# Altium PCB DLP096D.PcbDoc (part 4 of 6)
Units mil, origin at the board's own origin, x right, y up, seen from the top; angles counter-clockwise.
Board outline 4950 x 3159.45 mil, 8 copper layers (Top Layer, GND1, SIGNAL1, POWER1, POWER2, SIGNAL2, GND2, Bottom Layer), stack 60.4 mil thick; 328 components, 223 nets, 1380 pads, 856 vias.
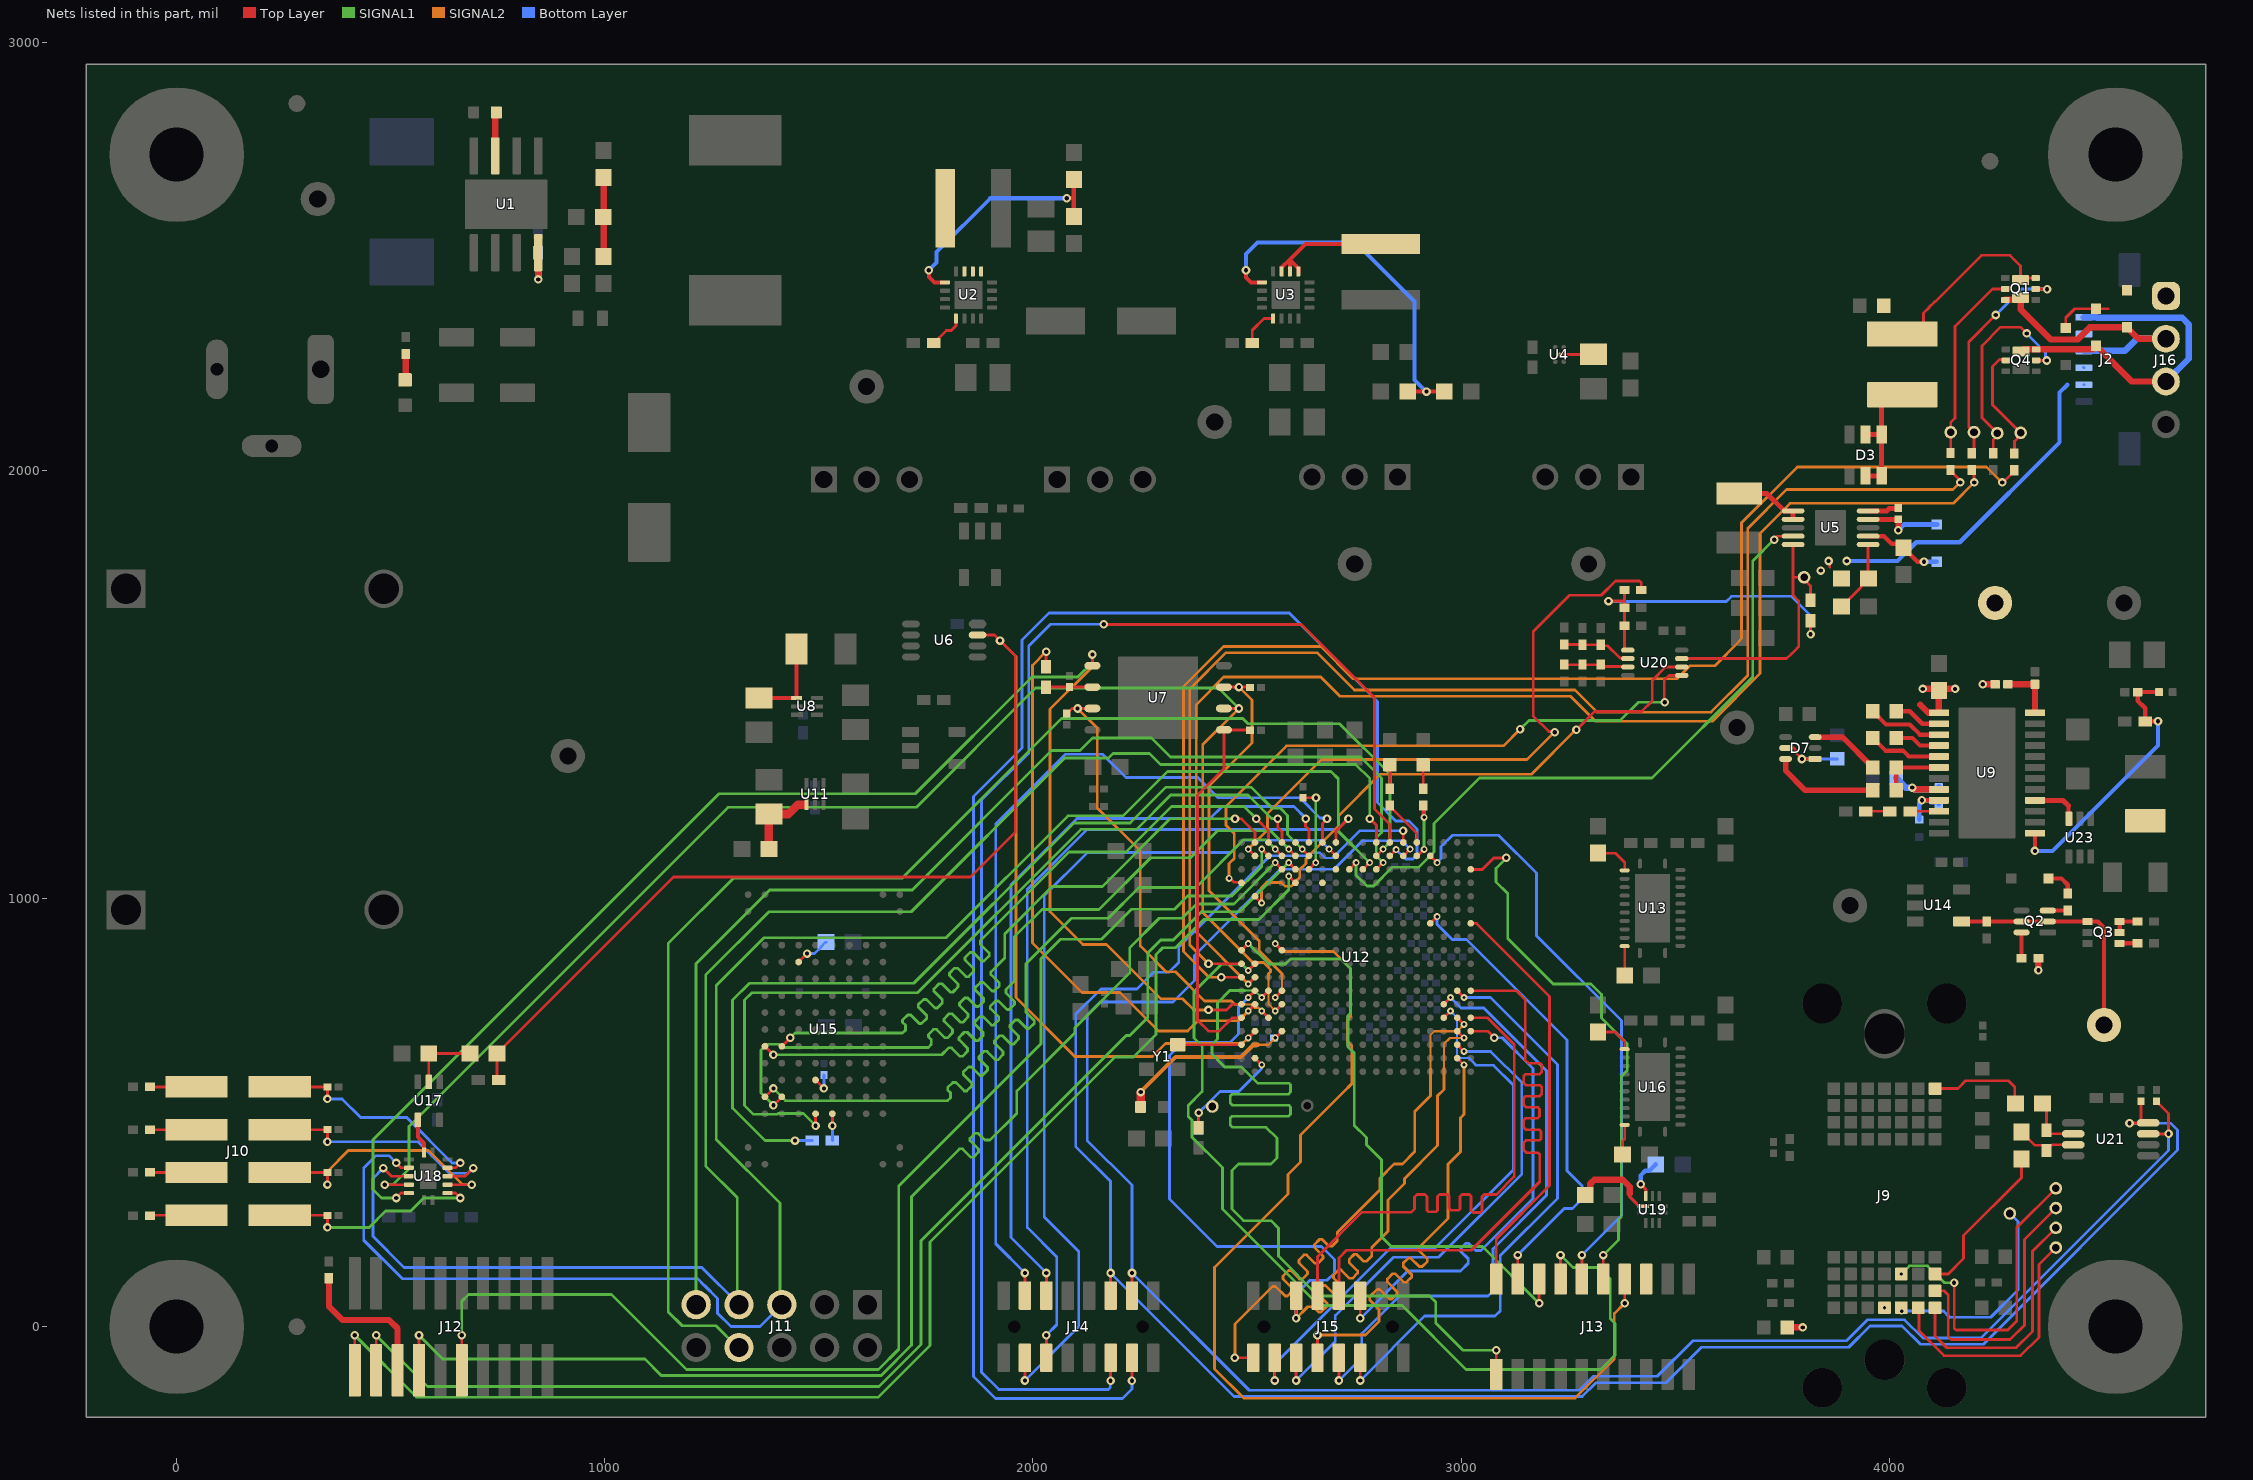
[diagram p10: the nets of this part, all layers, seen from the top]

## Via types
v1: diameter 20, hole 10, Top Layer to Bottom Layer, tented top, 596 vias
v2: diameter 16, hole 8, Top Layer to Bottom Layer, tented both sides, 126 vias
v3: diameter 16, hole 8.01, Top Layer to Bottom Layer, tented top, 63 vias
v4: diameter 19.68, hole 7.87, Top Layer to Bottom Layer, 37 vias
v5: diameter 16, hole 8.02, Top Layer to Bottom Layer, tented bottom, 22 vias
v6: diameter 24.8, hole 12.99, Top Layer to Bottom Layer, 6 vias
v7: diameter 19.68, hole 7.87, Top Layer to Bottom Layer, tented both sides, 6 vias

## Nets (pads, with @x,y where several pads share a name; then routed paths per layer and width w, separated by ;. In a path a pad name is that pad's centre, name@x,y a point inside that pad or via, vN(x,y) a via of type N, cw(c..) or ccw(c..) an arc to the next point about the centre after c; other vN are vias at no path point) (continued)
GPMC_AD7: J13.19 U12.M3 | length 2236.3
  Top Layer w6.5: v2(2534.33,768.95) U12.M3@2550.08,784.7 ; J13.19@3082.19,-111.32 v1(3082.19,-55.1)
  SIGNAL1 w5: 2495.5,784.95 2518.33,784.95 v2(2534.33,768.95)
  SIGNAL1 w6.5: 2495.5,784.95 2459.64,784.95 2431.08,756.38 2431.08,671.69 2418.03,658.65 2418.03,636.62 2440.47,614.19 2447.86,606.79 2486.79,606.79 2524.79,568.79 2597.91,568.79 2601.72,564.98 2601.72,548.01 2596.73,543.02 2464.64,543.02 2460.84,539.21 2460.84,522.24 2465.83,517.25 2597.91,517.25 2601.72,513.44 2601.72,496.47 2596.73,491.48 2464.64,491.48 2460.84,487.67 2460.84,470.7 2465.83,465.71 2544.53,465.71 2569.77,440.47 2569.77,393.93 2555.62,379.78 2479.74,379.78 2464.66,364.7 2464.66,274.82 2491.77,247.72 2555.51,247.72 2573.19,230.04 2573.19,164.79 2666.06,71.92 2926.5,71.92 2940.69,57.72 2940.69,8.97 3004.76,-55.1 v1(3082.19,-55.1)
GPMC_ADVn_ALE: J13.12 U12.B15 | length 1402.7
  Top Layer w6.5: U12.B15@2928.03,1099.66 v2(2943.78,1083.91) ; J13.12@3282.19,111.13 v1(3282.19,167.35)
  Bottom Layer w6.5: v2(2943.78,1083.91) 2953.36,1093.49 2953.36,1121.52 2979.73,1147.89 3087.65,1147.89 3175.95,1059.58 3175.95,913.14 3374.31,714.78 3374.31,259.47 v1(3282.19,167.35)
GPMC_BE0n_CLE: J13.10 U12.C18 | length 1290.3
  Top Layer w6.5: U12.C18@3022.52,1068.17 3049.34,1068.17 3076.19,1095.01 v1(3105.67,1095.01) ; J13.10@3332.19,111.13 v1(3332.19,167.35)
  SIGNAL1 w6.5: v1(3105.67,1095.01) 3081.3,1070.64 3081.3,1038.93 3108.82,1011.41 3108.82,906.78 3215.24,800.36 3303.63,800.36 3327.73,776.26 3327.73,720.98 3388.17,660.54 3388.17,598.08 3373.84,583.74 3373.84,255.83 3367.57,249.56 3367.57,202.73 v1(3332.19,167.35)
GPMC_CSn0: J13.8 U12.J4 | length 2494.1
  Top Layer w6.5: v2(2565.82,894.94) U12.J4@2581.57,879.19 ; v1(3382.19,54.91) J13.8@3382.19,111.13
  SIGNAL2 w6.5: v2(2565.82,894.94) 2584.25,876.52 2701.72,876.52 2741.53,836.71 2741.53,723.94 2734.02,716.44 2734.02,666.02 2744.49,655.55 2744.49,567.57 2723.83,546.91 2624.76,447.84 2624.76,384.55 2595.67,355.45 2595.67,310.4 2423.99,138.72 2423.99,-98.59 2492.34,-166.94 3265.93,-166.94 3357.83,-75.04 3357.83,30.54 v1(3382.19,54.91)
GPMC_LOCK: J13.6
GPMC_OEn_REn: J13.16 U12.J1 | length 1445.2
  Top Layer w6.5: U12.J1@2487.08,879.19 v2(2502.83,894.94) ; v1(3182.19,54.91) J13.16@3182.19,111.13
  SIGNAL1 w6.5: v2(2502.83,894.94) 2550.88,846.89 2589.29,846.89 2601.41,859.02 2719.21,859.02 2741.64,836.59 2741.64,732.82 2735.95,727.12 2735.95,653.31 2750.42,638.83 2750.42,470.25 2779.1,441.57 2779.1,424.99 2814.04,390.05 2814.04,209.97 2836.89,187.12 3049.98,187.12 v1(3182.19,54.91)
GPMC_WAIT0: J13.20 U12.G18 | length 966.4
  Top Layer w6.5: U12.G18@3022.52,942.18 3035.72,942.18 3206.39,771.51 3206.39,329.58 3082.19,205.38 J13.20@3082.19,111.13
GPMC_WEn: J13.14 U12.K2 | length 2207.1
  Top Layer w6.5: v2(2502.83,831.95) U12.K2@2518.58,847.69 ; J13.14@3232.19,111.13 v1(3232.19,167.35)
  SIGNAL1 w6.5: v2(2502.83,831.95) 2488.23,846.55 2440.43,846.55 2376.1,782.22 2376.1,674.73 2395.15,655.68 2395.15,549.2 2362.78,516.83 2362.78,490.7 2371.39,482.09 2371.39,442.62 2442.38,371.63 2442.38,275.27 2668.28,49.37 2862.55,49.37 3011.69,-99.77 3326.16,-99.77 3359.49,-66.44 3359.49,7.75 3348.41,18.84 3348.41,111.19 3321.08,138.52 3261.02,138.52 v1(3232.19,167.35)
GPMC_WPn: J13.18 U12.G15 | length 1102.7
  Top Layer w6.5: U12.G15@2928.03,942.18 v2(2943.78,957.93) ; J13.18@3132.19,111.13 v1(3132.19,167.35)
  Bottom Layer w6.5: v2(2943.78,957.93) 2943.78,940.07 2979.28,904.57 3012.89,904.57 3247.59,669.87 3247.59,364.17 3282.88,328.88 3282.88,299.2 3259.76,276.08 3240.93,276.08 v1(3132.19,167.35)
GREEN_CATH: D9.2 J2.1 J16.3 Q4.6 Q4.7 | length 786
  Top Layer w15: Q4.7@4307.78,2277.85 4312.71,2282.77 Q4.6@4343.22,2282.77 4474.88,2282.77 D9.2@4483.21,2291.1 4566.69,2207.62 J16.3@4646.25,2207.62
  Bottom Layer w15: J2.1@4454.68,2357.79 4484.78,2357.79 4486.25,2356.32 4684.24,2356.32 4699.79,2340.76 4699.79,2261.16 J16.3@4646.25,2207.62
GREEN_LED_EN: R80.1 U12.L1 | length 3182.1
  Top Layer w6.5: v1(2439.95,816.2) U12.L1@2487.08,816.2 ; v1(4263.67,1971.88) 4265.76,1971.88 4292.24,1998.36 R80.1@4292.24,2000.33 R80.1@4292.55,2000.02
  SIGNAL2 w6.5: v1(2439.95,816.2) 2411.57,816.2 2351.69,876.09 2351.69,1495.14 2445.22,1588.67 2672.35,1588.67 2747.73,1513.3 3362.61,1513.3 3503.8,1513.3 3534.39,1543.88 3592.57,1543.88 3648.81,1600.12 3648.81,1601.31 3654.99,1607.49 3654.99,1877.78 3785.29,2008.08 4227.47,2008.08 v1(4263.67,1971.88)
I2C0_SCL: J14.6 R86.1 U12.A13 U21.8 | length 4851.7
  Top Layer w6.5: J14.6@2181.28,72.44 v1(2181.28,125.42) ; v1(2864.47,1158.59) 2864.75,1158.31 2864.75,1131.44 U12.A13@2865.04,1131.16 ; v1(4561.08,475.36) 4561.43,475.71 4604.5,475.71 U21.8@4604.84,476.05 4593.34,476.05 4588.16,481.23 R86.1@4588.16,526.69
  Bottom Layer w5: 2553.56,1099.91 2644.94,1099.91 2652,1106.97 2670.03,1106.97 2681.91,1095.09 2700.59,1095.09 2712.64,1107.14
  Bottom Layer w6.5: 2553.56,1099.91 2340.54,886.89 2340.54,850.64 2317.96,828.05 2281.98,828.05 2242.57,788.65 2158.57,788.65 2099.77,729.85 2099.77,421.33 2181.28,339.81 v1(2181.28,125.42) 2469.54,-162.84 3282.79,-162.84 3314.68,-130.95 3478.33,-130.95 3561.19,-48.08 3905.28,-48.08 3955.07,1.7 4030,1.7 4072.6,-40.89 4220.29,-40.89 4673.58,412.4 4673.58,459.1 4657.32,475.36 v1(4561.08,475.36) ; 2712.64,1107.14 2764.09,1158.59 v1(2864.47,1158.59)
I2C0_SDA: J14.4 R85.1 U12.B13 U21.7 | length 4682.7
  Top Layer w6.5: J14.4@2231.28,72.44 v1(2231.28,125.42) ; U12.B13@2865.04,1099.66 v2(2880.79,1115.41) ; R85.1@4624.63,526.82 4624.63,526.03 4652.46,498.2 v1(4652.46,450.35) 4652.4,450.4 4604.9,450.4 U21.7@4604.84,450.46 U21.7@4625.23,450.46
  Bottom Layer w5: 2591.54,1068.41 2696.47,1068.41
  Bottom Layer w6.5: 2591.54,1068.41 2578.86,1068.41 2377.07,866.63 2377.07,808.78 2326.93,758.64 2157.12,758.64 2126.56,728.09 2126.56,435.31 2231.28,330.59 v1(2231.28,125.42) 2505.17,-148.47 3276.83,-148.47 3309.5,-115.8 3458.19,-115.8 3541.2,-32.79 3899.83,-32.79 3948.7,16.08 4035.95,16.08 4078.55,-26.52 4214.33,-26.52 4652.46,411.61 v1(4652.46,450.35) ; 2696.47,1068.41 2703.19,1068.41 2769.71,1134.94 2861.26,1134.94 v2(2880.79,1115.41)
I2C1_SCL: U12.D7
I2C1_SDA: U12.C8
LED_ANODE: C70.1 D1.1 D9.1 D10.1 J2.2 J2.4 J2.5 J16.1 L4.2 Q1.6 Q1.7 R12.2 | length 1399.2
  Top Layer w6.5: v1(3858.2,1788.47) 3860.88,1785.79 3860.88,1774.02 ; R12.2@3879.93,1739.31 R12.2@3888.25,1747.63 ; R12.2@3887.27,1747.63 R12.2@3888.25,1747.63 ; R12.2@3900.86,1760.23 R12.2@3888.25,1747.63 ; L4.2@4030.55,2318.66 4053.67,2318.66 4080.19,2345.19 4080.19,2367.33 4092.94,2380.08 4092.94,2381.06 4105.69,2393.81 4106.68,2393.81 4215.2,2502.34 4282.19,2502.34 4306.7,2477.83 Q1.7@4306.7,2444.58 4311.62,2449.5 Q1.6@4342.13,2449.5 ; D10.1@4412.25,2332.92 4412.25,2356.6 4433.36,2377.72 D9.1@4483.21,2377.72 4511.75,2377.72 ; D1.1@4554.96,2420.93 D1.1@4563.77,2412.11 ; J16.1@4641.76,2412.11 J16.1@4646.25,2407.62
  Bottom Layer w6.5: J2.4@4453.59,2240.76 J2.4@4454.68,2239.68 ; J2.5@4454.49,2200.12 J2.5@4454.68,2200.31
  Bottom Layer w10: v1(3900.86,1788.47) 4019.07,1788.47 4062.93,1832.33 4164.66,1832.33 4397.86,2065.53 4397.86,2181.99 4416.01,2200.14
  other v1: 3839.75,1766.01
LED_DRV_EN: U5.9 U12.C9 | length 1618.8
  Top Layer w6.5: U12.C9@2739.05,1068.17 v2(2754.8,1083.91) ; v1(3731.25,1838.23) 3739.45,1846.43 U5.9@3775.35,1846.43
  SIGNAL1 w6.5: v2(2754.8,1083.91) 2754.8,1054.5 2780,1029.3 2796.03,1029.3 2840.03,1073.3 2901.23,1073.3 2936.93,1109.01 2936.93,1167.9 2936.93,1175.01 3043.29,1281.37 3445.82,1281.37 3681.26,1516.81 3681.26,1788.24 v1(3731.25,1838.23)
LIN2_RXD: J14.13 U12.B8 | length 2020.6
  Top Layer w6.5: v1(1981.28,-125.61) J14.13@1981.28,-72.63 ; v2(2691.81,1115.41) U12.B8@2707.56,1099.66
  Bottom Layer w6.5: v1(1981.28,-125.61) 2106.92,0.03 2106.92,175.56 2026.33,256.15 2026.33,1006.8 2127.22,1107.69 2462.33,1107.69 2490.66,1136.02 2671.2,1136.02 v2(2691.81,1115.41)
LIN2_TXD: J14.11 U12.A8 | length 2018.5
  Top Layer w6.5: J14.11@2031.28,-72.63 v1(2031.28,-19.66) ; U12.A8@2707.56,1131.16 2707.56,1157.09 v1(2736.82,1186.35)
  Bottom Layer w6.5: v1(2031.28,-19.66) 2055.57,4.62 2055.57,162.72 1986.82,231.46 1986.82,1021.85 2126.46,1161.5 2440.47,1161.5 2711.97,1161.5 2727.68,1177.21 v1(2736.82,1186.35)
MCAN2_RX: J14.5 U12.A12 | length 3383.1
  Top Layer w6.5: v1@2165.8,1640.39 2626.49,1640.39 2797.92,1468.96 2797.92,1234.56 2797.67,1234.31 2797.67,1208.92 2833.54,1173.05 U12.A12@2833.54,1131.16 ; v1(2181.23,-126.35) 2181.23,-72.68 J14.5@2181.28,-72.63
  Bottom Layer w6.5: v1(2165.06,1640.77) 2040.84,1640.77 1990.16,1590.09 1990.16,1340.36 1879.93,1230.13 1879.93,-106.4 1920.26,-146.73 2176.17,-146.73 2180.61,-142.29 2180.61,-126.97 v1(2181.23,-126.35)
MCAN2_TX: J14.3 U12.B12 | length 3679.3
  Top Layer w6.5: v1(2231.22,-126.35) 2231.22,-72.7 J14.3@2231.28,-72.63 ; U12.B12@2833.54,1099.66 v2(2848.21,1114.39)
  Bottom Layer w6.5: v1(2231.22,-126.35) 2231.22,-145.15 2208.84,-167.52 1912.68,-167.52 1861.27,-116.11 1861.27,1238.54 1974.6,1351.86 1974.6,1604.14 2037.23,1666.78 2598.47,1666.78 2804.72,1460.53 2804.72,1224.08 2847.35,1181.45 2878.02,1181.45 2891.57,1167.9 2897.28,1162.19 2897.28,1102.43 2887.22,1092.37 2870.23,1092.37 v2(2848.21,1114.39)
NetC1_1: C1.1 U1.7 | length 102.4
  Top Layer w15: U1.7@744.28,2734.87 744.28,2833.61 C1.1@746.89,2836.22
NetC2_1: C2.1 C3.2 R1.2 | length 185
  Top Layer w15: C3.2@997.4,2499.3 997.4,2591.79 R1.2@997.4,2684.27
NetC6_1: C6.1 U2.9 | length 85.7
  Top Layer w6.5: C6.1@1767.84,2297.32 1797.6,2327.09 1809.08,2327.09 1820.01,2338.02 U2.9@1820.03,2354.73
NetC8_1: C8.1 U3.9 | length 90.1
  Top Layer w6.5: C8.1@2512.18,2297.27 2512.18,2327.27 2539.64,2354.73 U3.9@2560.86,2354.73
NetC17_1: C17.1 D501.1 U5.4 | length 191.3
  Top Layer w11.81: U5.4@3950.54,1885.8 4020.99,1885.8 v1(4020.99,1860.31)
  Bottom Layer w11.81: v1(4020.99,1860.31) 4034.07,1873.39 D501.1@4110.9,1873.39
NetC17_2: C17.2 D3.1 D3.2 D3.5 D3.6 L4.1 U5.5 | length 371.8
  Top Layer w11.81: D3.5@3944.95,1987.45 D3.6@3982.35,1987.45 D3.1@3982.35,2083.91 ; D3.2@3944.95,2083.91 D3.1@3982.35,2083.91 ; U5.5@3950.54,1905.48 3994.12,1905.48 3999.7,1911.06 4020.12,1911.06 C17.2@4020.99,1911.94 ; L4.1@4030.55,2176.93 4005.97,2176.93 3982.35,2153.31 D3.1@3982.35,2083.91
NetC18_1: C18.1 D501.2 U5.2 | length 185.1
  Top Layer w10: U5.2@3950.54,1846.43 3987.85,1846.43 4005.52,1828.75 4024.12,1828.75 4066.1,1786.78 v1(4081.16,1786.78)
  Bottom Layer w10: v1(4081.16,1786.78) D501.2@4110.9,1786.78
NetC20_1: C20.1 R13.2 R14.2 R76.2 U20.1 | length 755.8
  Top Layer w6: R76.2@3815.8,1649.35 3816.16,1649 v1(3816.16,1617.65)
  Top Layer w6.5: v1(3344.3,1694.88) 3381.37,1694.88 ; R14.2@3381.37,1720.69 3381.37,1694.88 ; U20.1@3389.43,1580.2 3383.83,1580.2 3381.37,1582.66 C20.1@3381.37,1637.65 R13.2@3381.37,1679.17 3381.37,1694.88
  Bottom Layer w6.5: v1(3344.3,1694.88) 3345.6,1693.58 3619.36,1693.58 3631.72,1705.95 3771.76,1705.95 3816.16,1661.54 v1(3816.16,1617.65)
NetC21_1: C21.1 R12.1 U5.1 | length 170.6
  Top Layer w6.5: C21.1@3888.25,1682.72 3889.24,1682.72 3934.81,1728.3 3934.81,1732.18 3950.26,1747.63 3950.54,1747.63 U5.1@3950.54,1826.74
NetC27_1: C27.1 U9.14 | length 111.3
  Top Layer w10: C27.1@4016.62,1437.45 4048.05,1437.45 4077.05,1408.45 U9.14@4115.92,1408.45
NetC27_2: C27.2 U9.15 | length 177
  Top Layer w10: C27.2@3961.5,1437.45 3992.41,1406.54 4047.76,1406.54 4071.44,1382.86 U9.15@4115.92,1382.86
NetC29_2: C29.2 R20.1 R21.2 U9.1 | length 642.5
  Top Layer w10: v1(4340.33,1111.19) U9.1@4340.33,1152.54 ; v1(4627.66,1413.83) C29.2@4597.85,1413.83 4597.85,1444.44 4580.17,1462.12 R20.1@4580.17,1482.23 R21.2@4630.17,1482.23
  Bottom Layer w10: v1(4340.33,1111.19) 4381.27,1111.19 4627.66,1357.58 v1(4627.66,1413.83)
NetC33_1: C33.1 U9.16 | length 106.7
  Top Layer w10: C33.1@4016.62,1375.08 4053.93,1375.08 4071.75,1357.27 U9.16@4115.92,1357.27
NetC33_2: C33.2 U9.17 | length 172.4
  Top Layer w10: C33.2@3961.5,1375.08 3991.11,1345.48 4032.05,1345.48 4045.85,1331.68 U9.17@4115.92,1331.68
NetC34_1: C34.1 D7.3 | length 164.1
  Top Layer w13: D7.3@3826.84,1377.2 3890.38,1377.2 C34.1@3961.5,1306.09
NetC34_2: C34.2 C37.1 U9.18 | length 152.5
  Top Layer w10: C37.1@4016.62,1252.85 C34.2@4016.62,1306.09 U9.18@4115.92,1306.09
NetC37_2: C37.2 D7.6 | length 249.9
  Top Layer w13: D7.6@3757.81,1326.02 3757.81,1298.89 3803.84,1252.85 C37.2@3961.5,1252.85
NetC40_2: C40.2 R33.1 | length 59.7
  Top Layer w6.5: C40.2@3941.57,1203.72 R33.1@4001.26,1203.72
NetC51_1: C51.1 R46.1 U17.2 | length 162.2
  Top Layer w6.5: U17.2@588.87,571.84 C51.1@588.87,638.09 R46.1@684.85,638.09
NetC66_1: C66.1 R30.2 R49.2 U20.2 | length 162.3
  Top Layer w6: R30.2@3240.8,1593.39 3283.08,1593.39 R49.2@3283.55,1592.91 ; R49.2@3283.55,1592.91 C66.1@3326.3,1592.94 3328.62,1590.62 3342.13,1590.62
  Top Layer w6.5: 3342.13,1590.62 3371.12,1561.63 3388.32,1561.63 U20.2@3389.43,1560.52
NetC68_1: C68.1 R50.2 R51.2 U20.3 | length 150.9
  Top Layer w6: R50.2@3240.8,1546.26 3283.36,1546.26 R51.2@3283.55,1546.44 C68.1@3326.3,1546.43
  Top Layer w6.5: C68.1@3326.3,1546.07 3330.42,1541.94 3377.04,1541.94 3378.15,1540.83 U20.3@3389.43,1540.83
NetC72_1: C72.1 R83.1 U21.2 | length 132.1
  Top Layer w6.5: R83.1@4357.66,521.14 4367.32,511.47 C72.1@4367.32,458.79 4375.66,450.46 U21.2@4429.64,450.46
NetC72_2: C72.2 R84.1 U21.3 | length 145.7
  Top Layer w6.5: R84.1@4308.7,455.01 4308.7,454.02 4324.15,438.57 4325.14,438.57 4339.66,424.05 4358.76,424.05 C72.2@4367.32,415.49 ; C72.2@4367.32,411.55 C72.2@4367.32,415.49 ; U21.3@4429.64,424.87 4380.64,424.87 4379.82,424.05 4375.88,424.05 C72.2@4367.32,415.49
NetC504_1: C504.1 D7.1 D7.5 | length 166.1
  Top Layer w6.5: D7.5@3757.81,1351.61 3777.12,1351.61 3783.7,1345.03 3783.7,1338.43 v1(3796.1,1326.02) D7.1@3826.84,1326.02
  Bottom Layer w6.5: v1(3796.1,1326.02) C504.1@3878.72,1326.02
NetC505_1: C505.1 R503.1 U9.20 | length 176.6
  Top Layer w15: v1(4053.64,1259.16) 4057.9,1254.9 U9.20@4115.92,1254.9
  Bottom Layer w15: C505.1@4016.62,1281.53 4038.99,1259.16 v1(4053.64,1259.16) 4057.9,1254.9 4110.56,1254.9 R503.1@4115.92,1260.27
NetC526_1: C526.1 U15.E4 | length 83.7
  Top Layer w6.5: U15.E4@1452.77,851.78 v1(1472.46,871.47)
  Bottom Layer w6.5: v1(1472.46,871.47) 1489.96,871.47 1504.52,886.02 1504.52,887.01 1515.72,898.21 C526.1@1516.71,898.21
NetD2_2: D2.2 R4.1 | length 51.8
  Top Layer w15: D2.2@534.88,2220.31 R4.1@534.88,2272.07
NetD5_2: D5.2 R31.1 | length 55.6
  Top Layer w6.5: R31.1@2833.82,1256.42 D5.2@2833.82,1312.07
NetD6_2: D6.2 R32.1 | length 55.6
  Top Layer w6.5: R32.1@2911.38,1256.42 D6.2@2911.38,1312.07
NetD8_2: D8.2 R38.2 | length 72.3
  Top Layer w10: D8.2@4371.61,1046.98 4402.37,1046.98 4416.95,1032.4 R38.2@4416.95,1011.44
NetJ9_E13: J9.E13 TP20.1 | length 758.3
  Top Layer w6.5: v1(4151.39,102.67) 4151.95,102.11 4151.95,-4 4155.75,-7.8 4276.77,-7.8 4297.8,13.23 4297.8,231.93 TP20.1@4389.08,323.21
  SIGNAL1 w6.5: v5(4028.26,123.11) 4047.38,142.23 4089.64,142.23 4129.2,102.67 v1(4151.39,102.67)
NetJ9_E15: J9.E15 TP13.1 | length 498.8
  Top Layer w6.5: J9.E15@4028.26,44.37 4028.91,43.71 v5(4028.91,36.42)
  Bottom Layer w6.5: v5(4028.91,36.42) 4127.12,36.42 4141.4,22.14 4237.04,22.14 4300.66,85.76 4300.66,245.62 TP13.1@4281.77,264.5
NetJ9_F15: J9.F15 TP18.1 | length 602.5
  Top Layer w6.5: J9.F15@4067.63,44.37 4069.73,42.26 4069.73,-9.33 4128.08,-67.67 4306.99,-67.67 4349.58,-25.08 4349.58,145.34 TP18.1@4389.08,184.84
NetJ9_G2: J9.G2 R83.2 | length 238.8
  Top Layer w6.5: J9.G2@4107,556.18 4160.3,556.18 4178.47,574.35 4278.21,574.35 4293.26,559.3 4293.26,522.54 R83.2@4294.66,521.14
NetJ9_G13: J9.G13 R84.2 | length 370.4
  Top Layer w6.5: J9.G13@4107,123.11 4137.68,123.11 4173.72,159.15 4173.72,212.95 4308.7,347.93 R84.2@4308.7,392.01
NetJ9_G14: J9.G14 TP19.1 | length 639.9
  Top Layer w6.5: J9.G14@4107,83.74 4128.47,83.74 4137.57,74.64 4137.57,-22.83 4144.89,-30.15 4282.35,-30.15 4315.83,3.33 4315.83,203.84 TP19.1@4395.34,283.35
NetJ9_G15: J9.G15 TP21.1 | length 585.1
  Top Layer w6.5: J9.G15@4107,44.37 4107,-21.66 4134.41,-49.07 4296.17,-49.07 4334.38,-10.85 4334.38,176.27 TP21.1@4389.08,230.96
NetJ10_2: J10.2 R71.2 | length 111.4
  Top Layer w6.5: R71.2@-65.59,260.2 J10.2@45.83,260.2
NetJ10_4: J10.4 R68.2 | length 111.4
  Top Layer w6.5: R68.2@-65.59,360.2 J10.4@45.83,360.2
NetJ10_6: J10.6 R64.2 | length 111.4
  Top Layer w6.5: R64.2@-65.59,460.2 J10.6@45.83,460.2
NetJ10_8: J10.8 R48.2 | length 111.4
  Top Layer w6.5: R48.2@-65.59,560.2 J10.8@45.83,560.2
NetJ12_5: J12.5 R75.2 | length 344.9
  Top Layer w14.5: R75.2@355.48,113.28 355.48,47.71 387.65,15.54 496.21,15.54 515.94,-4.19 J12.5@515.94,-101.59
NetL2_1: L2.1 U2.1 U2.2 U2.3
NetL3_1: L3.1 U3.1 U3.2 U3.3 | length 326.1
  Top Layer w9.4: U3.3@2580.55,2464.97 2580.55,2473.42 2600.23,2493.1 ; U3.2@2600.23,2464.97 2600.23,2491.74 ; U3.1@2619.92,2464.97 2619.92,2472.06 2600.23,2491.74 ; L3.1@2812.21,2528.89 2636.02,2528.89 2600.23,2493.1 ; 2600.23,2491.74 2600.23,2493.1
NetL5_1: L5.1 U4.B2 | length 79.9
  Top Layer w8: U4.B2@3229.8,2270.72 L5.1@3309.74,2270.72
NetL6_1: L6.1 U9.4 U23.6 | length 120.1
  Top Layer w10: 4418.43,1216.91 4418.43,1203.63 U23.6@4421.2,1200.86 ; L6.1@4578.1,1182.03 L6.1@4597.78,1182.03
  Top Layer w12: U9.4@4340.33,1229.31 4406.03,1229.31 4418.43,1216.91
NetQ1_2: Q1.2 R78.2 TP2.1 | length 453.9
  Top Layer w6.5: R78.2@4143.06,2040.67 4143.43,2041.04 4143.43,2111.65 4153.85,2122.08 4153.85,2336.56 4241.21,2423.91 Q1.2@4271.26,2423.91
NetQ1_5: Q1.5 R79.2 TP3.1 | length 527.5
  Top Layer w6: R79.2@4192.79,2040.11 4197.91,2045.23 TP3.1@4197.91,2089.2
  Top Layer w6.5: TP3.1@4197.91,2089.2 4185.72,2101.39 4185.72,2300.19 v1@4248.39,2362.86 ; Q1.5@4342.13,2423.91 4342.37,2423.68 4368.4,2423.68 v1(4368.64,2423.44)
  Bottom Layer w6.5: v1(4248.75,2363) 4309.19,2423.44 v1(4368.64,2423.44)
NetQ2_2: Q2.2 Q2.5 Q3.4 R39.2 TP12.1 U14.4 | length 566
  Top Layer w10: U14.4@4168.92,946.48 R39.2@4227.71,946.48 Q2.5@4309.04,946.48 Q2.2@4370.2,946.48 Q3.4@4463.25,946.48 4486.97,946.48 4501.69,931.76 TP12.1@4501.69,704.62
NetQ2_3: Q2.3 R38.1 | length 46.8
  Top Layer w10: Q2.3@4370.2,972.07 R38.1@4416.95,972.07
NetQ2_6: Q2.6 R42.1 | length 60.6
  Top Layer w10: R42.1@4309.04,860.32 Q2.6@4309.04,920.89
NetQ3_1: Q3.1 R41.2 | length 41.3
  Top Layer w10: Q3.1@4538.06,895.3 R41.2@4579.41,895.3
NetQ3_2: Q3.2 Q3.3 R40.2 | length 66.9
  Top Layer w10: Q3.2@4538.06,920.89 Q3.3@4538.06,946.48 R40.2@4579.41,946.48
NetQ4_2: Q4.2 R80.2 TP14.1 | length 274.7
  Top Layer w6.5: Q4.2@4272.35,2257.18 4270.51,2259.02 4257.61,2259.02 4241.43,2242.84 4241.43,2153.39 TP14.1@4306.86,2087.97 4306.86,2082.54 4292.24,2067.92 R80.2@4292.24,2039.7
NetQ4_5: Q4.5 R81.2 TP15.1 | length 504.8
  Top Layer w6: R81.2@4242.51,2040.11 4242.51,2070.91 4252.38,2080.78 TP15.1@4252.38,2087.15
  Top Layer w6.5: TP15.1@4252.38,2087.15 4216.44,2123.08 4216.44,2290.97 4260.07,2334.6 4306.15,2334.6 v1@4320.28,2320.46 ; Q4.5@4343.22,2257.18 4343.4,2256.99 4367.51,2256.99 v1(4367.7,2256.8)
  Bottom Layer w6.5: v1(4320.88,2319.96) 4365.04,2275.8 4365.04,2259.47 v1(4367.7,2256.8)
NetR6_2: R6.2 R9.1 U2.5 | length 567.9
  Top Layer w9.4: v1(1756.8,2467.85) 1756.8,2452.32 1769.74,2439.38 U2.5@1794.44,2439.38
  Top Layer w10: v1(2078.95,2635.71) 2079.66,2636.42 2095.46,2636.42 ; R9.1@2095.46,2593.12 2095.46,2636.42 ; R6.2@2095.46,2679.72 2095.46,2636.42
  Bottom Layer w9.4: v1(1756.8,2467.85) 1774.27,2485.32 1774.27,2509.74 1900.24,2635.71 v1(2078.95,2635.71)
NetR7_1: R7.1 R8.2 U3.5 | length 866.4
  Top Layer w9.4: v1(2497.63,2467.85) 2497.63,2451.11 2509.36,2439.38 U3.5@2535.27,2439.38
  Top Layer w10: R7.1@2875.37,2184.26 v1(2919.17,2184.26) R8.2@2960.59,2184.26
  Bottom Layer w9.4: v1(2497.63,2467.85) 2497.63,2505.78 2524.28,2532.43 2752.96,2532.43 2890.87,2394.51 2890.87,2211.46 2918.07,2184.26 v1(2919.17,2184.26)
NetR11_1: R11.1 U5.6 U5.7 | length 162.1
  Top Layer w11.81: R11.1@3649.76,1946.03 3714.13,1946.03 3754.68,1905.48 U5.6@3775.35,1905.48 U5.7@3775.35,1885.8
NetR15_2: R15.2 R24.1 U8.1 | length 201.6
  Top Layer w9.8: R24.1@1360.62,1468.49 U8.1@1447.66,1468.49 R15.2@1447.66,1583.01
NetR16_2: R16.2 R18.2 U7.6 | length 107.9
  Top Layer w6.5: R16.2@2031,1493.98 R18.2@2085.41,1493.98 U7.6@2138.92,1493.98
NetR17_2: R17.2 R19.1 U9.12 | length 129.7
  Top Layer w15: R19.1@4277.09,1500.46 R17.2@4340.33,1500.46 U9.12@4340.33,1434.04
NetR27_2: R27.2 R36.1 U11.1 | length 173.9
  Top Layer w20: R36.1@1383.27,1115.55 R27.2@1383.27,1197.49 1428.89,1197.49 1450.99,1219.58 1466.07,1219.58
NetR33_2: R33.2 U9.22 | length 67.4
  Top Layer w6.5: R33.2@4048.5,1203.72 U9.22@4115.92,1203.72
NetR34_2: R34.2 U13.2 | length 89.7
  Top Layer w6.5: R34.2@3319.63,1106.01 3360.06,1106.01 3382.11,1083.97 U13.2@3382.11,1065.87
NetR43_2: R43.2 U13.11 | length 68.7
  Top Layer w6.5: R43.2@3382.11,820.04 U13.11@3382.11,888.71
NetR44_2: R44.2 U16.2 | length 89.7
  Top Layer w6.5: R44.2@3319.63,688.52 3360.06,688.52 3382.11,666.48 U16.2@3382.11,648.38
NetR62_2: R62.2 R519.1 TP22.1 U12.U2 | length 290.3
  Top Layer w6.5: R62.2@2386.96,464.91 v1(2386.96,499.66) ; U12.U2@2518.58,627.22 v2(2534.33,611.47)
  Bottom Layer w6.5: R519.1@2386.96,464.91 v1(2386.96,499.66) 2411.27,523.97 2436.69,549.39 2480.54,549.39 2533.18,602.02 2533.18,610.33 v2(2534.33,611.47)
NetR66_2: R66.2 U16.11 | length 70.4
  Top Layer w6.5: R66.2@3377.11,402.55 3377.11,434.05 3382.11,439.05 U16.11@3382.11,470.85
NetR69_1: R69.1 U19.1 | length 198.6
  Top Layer w8: 3393.9,310.25 3393.9,303.25 3415.74,281.42 U19.1@3425.45,281.42
  Top Layer w15: R69.1@3289.83,307.91 3290.81,307.91 3302.01,319.11 3302.01,334.34 3310.8,343.13 3377.73,343.13 3393.9,326.95 3393.9,310.25
NetR76_1: R76.1 TP16.1 U5.10 U20.7 | length 614.3
  Top Layer w6.5: U20.7@3515.42,1560.52 3760.26,1560.52 3771.4,1571.66 3771.76,1571.66 3784.13,1584.04 3784.13,1584.39 3788.37,1588.63 3788.37,1695.35 3775.35,1708.37 3775.35,1751.12 ; U5.10@3775.35,1826.74 3775.35,1751.12 ; R76.1@3815.8,1696.6 3815.8,1730.43 3801.12,1745.11 TP16.1@3801.12,1750.42 3776.04,1750.42 3775.35,1751.12
NetR500_2: R500.2 U1.4 | length 124.6
  Top Layer w15: v1(844.28,2446.17) U1.4@844.28,2508.5
  Bottom Layer w15: v1(844.28,2446.17) R500.2@844.28,2508.5
NetR503_2: R503.2 R504.1 U9.21 | length 130.9
  Top Layer w10: v1(4076.3,1229.31) U9.21@4115.92,1229.31
  Bottom Layer w10: R504.1@4069.89,1184.18 4069.89,1222.9 v1(4076.3,1229.31) 4092.69,1229.31 4096.73,1225.28 4110.56,1225.28 R503.2@4115.92,1219.91
NetR505_1: R505.1 U15.M5 | length 59.5
  Top Layer w6.5: U15.M5@1492.14,576.19 v1(1511.83,556.51)
  Bottom Layer w6.5: v1(1511.83,556.51) R505.1@1511.83,588.17
NetR520_2: R520.2 U15.P6 | length 62.7
  Top Layer w6.5: v1(1531.51,469.61) U15.P6@1531.51,497.45
  Bottom Layer w6.5: R520.2@1531.51,434.77 v1(1531.51,469.61)
NetR532_2: R532.2 U19.10 | length 99.2
  Top Layer w7: v1(3419.28,332.87) 3431.36,320.79 U19.10@3431.36,305.04
  Bottom Layer w10: v1(3419.28,332.87) 3419.28,353.22 3430.28,364.22 3439.71,364.22 R532.2@3454.61,379.12
NetU12_T1: U12.T1 Y1.3 | length 148.8
  Top Layer w6.5: Y1.3@2338.24,658.72 U12.T1@2487.08,658.72
NetU17_4: U17.4 U18.8 | length 82.7
  Top Layer w9.8: U17.4@563.28,483.25 563.28,442.89 577.74,428.43 U18.8@577.74,406.53
PWM_SEL1: U12.E2 U20.6 | length 1317.2
  Top Layer w6.5: U12.E2@2518.58,1005.17 2518.58,1005.08 2534.01,989.65 v2(2534.01,989.56) ; v1(3269.34,1394.17) 3311.78,1436.61 3389.15,1436.61 3421.13,1436.61 3446.36,1461.84 3446.36,1509.71 3477.48,1540.83 U20.6@3515.42,1540.83
  SIGNAL2 w6.5: v2(2534.01,989.56) 2534.01,1025.87 2545.34,1037.2 2580.86,1037.2 2589.47,1028.58 2602.26,1028.58 2623.18,1049.49 2623.18,1067.55 2637.68,1082.05 2637.68,1093.38 2713.53,1169.23 2713.53,1192.94 2810.92,1290.33 3164.63,1290.33 v1@3267.6,1393.3
PWM_SEL2: U12.D1 U20.5 | length 1439.7
  Top Layer w6.5: v2(2457.96,1047.08) 2460.53,1047.08 2469.46,1038.15 2485.6,1038.15 U12.D1@2487.08,1036.67 ; v1@3476.69,1457.31 v1(3475.67,1458.32) 3474.54,1459.45 3474.54,1510.45 3485.24,1521.15 U20.5@3515.42,1521.15
  SIGNAL1 w6.5: v1(3137.74,1395.54) 3158.29,1416.09 3371.54,1416.09 3413.78,1458.32 v1(3475.67,1458.32)
  SIGNAL2 w6.5: v2(2457.96,1047.08) 2457.96,1081.65 2470.18,1093.87 2470.18,1151.83 2450.7,1171.32 2450.7,1215.17 2592.29,1356.76 3098.96,1356.76 v1(3137.74,1395.54)
R_W_LED_IADJ_PWM: R14.1 U12.B2 | length 1454.5
  Top Layer w6.5: v2(2502.83,1115.41) U12.B2@2518.58,1099.66 ; v1(3218.53,1388.75) 3217.25,1390.03 3204.88,1390.03 3168.27,1426.64 3168.27,1623.22 3253.55,1708.5 3327.2,1708.5 3360.36,1741.66 3416.94,1741.66 3420.74,1737.85 R14.1@3420.74,1720.69
  SIGNAL2 w6.5: v2(2502.83,1115.41) 2547.68,1160.25 2547.68,1198.89 2673.85,1325.06 3153.98,1325.06 v1@3216.8,1387.88
RED_WHITE_CATH: D1.2 J2.3 J16.2 Q1.3 Q1.8 | length 659.4
  Top Layer w15: Q1.3@4271.26,2398.32 4301.78,2398.32 Q1.8@4306.7,2403.24 4306.7,2376.45 4377.43,2305.72 4440.1,2305.72 4468.69,2334.31 D1.2@4554.96,2334.31 4581.65,2307.62 J16.2@4646.25,2307.62
  Bottom Layer w6.5: J16.2@4644.74,2307.62 J16.2@4646.25,2307.62
  Bottom Layer w15: J2.3@4454.68,2279.05 4550.3,2279.05 4578.87,2307.62 J16.2@4644.74,2307.62
RED_WHITE_LED_EN: R79.1 U12.L2 | length 3065.3
  Top Layer w6.5: v2(2502.83,800.45) U12.L2@2518.58,816.2 ; R79.1@4192.79,2000.74 4198.27,1995.25 v1(4198.27,1971.88) ; R79.1@4198.19,2000.74 R79.1@4198.27,2000.65
  SIGNAL2 w6.5: v2(2502.83,800.45) 2381.57,921.71 2381.57,1453.38 2445.42,1517.22 2672.05,1517.22 2716.79,1472.48 3255.48,1472.48 3313.85,1414.11 3586.82,1414.11 3698.22,1525.51 3698.22,1852.88 3768.42,1923.08 4149.47,1923.08 v1(4198.27,1971.88)
RMII1_CRS_DV: J15.10 U12.P18 | length 1287.7
  Top Layer w6.5: J15.10@2664.59,72.44 2664.59,163.42 2768.69,267.51 2883.72,267.51 2891.26,275.05 2891.26,302.6 2897.36,308.7 2915.38,308.7 2920.37,303.71 2920.37,272.12 2924.18,268.31 2941.16,268.31 2944.96,272.12 2944.96,303.71 2949.95,308.7 2967.98,308.7 2971.79,304.89 2971.79,276.8 2976.78,271.81 2993.75,271.81 2997.56,275.62 2997.56,303.71 3002.55,308.7 3019.52,308.7 3023.33,304.89 3023.33,271.8 3028.32,266.81 3045.29,266.81 3049.1,270.62 3049.1,303.71 3054.09,308.7 3082.23,308.7 3123.96,350.43 3123.96,658.62 3123.96,659.6 3073.74,709.81 3061.84,721.71 3060.86,721.71 U12.P18@3022.52,721.71
RMII1_RX_ER: J15.6 U12.R18 | length 1116.2
  Top Layer w6.5: v1(2764.59,19.47) J15.6@2764.59,72.44 ; U12.R18@3022.52,690.21 3062.49,690.21 v1(3077.71,674.99)
  Bottom Layer w6.5: v1(2764.59,19.47) 2875.46,130.34 2998.73,130.34 3016.61,148.23 3016.61,158.62 2999.26,175.98 2999.26,183.03 3011.26,195.04 3016.64,195.04 3033.45,178.23 3046.62,178.23 3167.94,299.55 3167.94,603.03 3095.98,674.99 v1(3077.71,674.99)
RMII1_RXD0: J15.9 U12.U17 | length 1129.1
  Top Layer w6.5: J15.9@2664.59,-72.63 v1(2664.59,-19.66) ; U12.U17@2991.02,627.22 v2(3006.77,611.47)
  SIGNAL2 w6.5: v1(2664.59,-19.66) 2776.47,-19.66 2808.35,12.21 2808.35,40.46 2786.56,62.24 2786.56,70.06 2803.21,86.71 2810.27,86.71 2832.61,64.38 2837.99,64.38 2850,76.38 2850,81.76 2827.66,104.1 2827.66,111.16 2840.41,123.9 2845.79,123.9 2865.65,104.04 2872.71,104.04 2884.71,116.04 2884.71,121.43 2864.85,141.29 2864.85,148.35 2876.85,160.35 2882.24,160.35 2902.1,140.49 2909.16,140.49 2921.16,152.49 2921.16,157.88 2901.3,177.74 2901.3,184.8 2969.27,252.76 2969.27,379.49 2998.54,408.76 2998.54,487.88 3006.77,496.11 v2(3006.77,611.47)
RMII1_RXD1: J15.11 U12.T17 | length 1216.3
  Top Layer w6.5: v1(2614.59,-125.61) J15.11@2614.59,-72.63 ; U12.T17@2991.02,658.72 v2(3006.77,642.97)
  Bottom Layer w6.5: v1(2614.59,-125.61) 2706.27,-33.93 2706.27,26.44 2842.14,162.31 2947.48,162.31 3141.77,356.59 3141.77,570.25 3069.05,642.97 v2(3006.77,642.97)
RMII1_TX_EN: J15.8 U12.M18 | length 1500.2
  Top Layer w6.5: J15.8@2714.59,72.44 2714.59,160.86 2732.42,178.68 3023.72,178.68 3183.67,338.63 3183.67,402.4 3179.86,406.2 3152.31,406.2 3146.21,412.3 3146.21,430.33 3151.2,435.32 3182.79,435.32 3186.6,439.13 3186.6,456.1 3182.79,459.91 3151.2,459.91 3146.21,464.9 3146.21,482.92 3150.02,486.73 3178.11,486.73 3183.1,491.72 3183.1,508.7 3179.29,512.5 3151.2,512.5 3146.21,517.49 3146.21,534.47 3150.02,538.27 3183.11,538.27 3188.1,543.27 3188.1,560.24 3184.29,564.05 3151.2,564.05 3146.21,569.04 3146.21,586.01 3150.02,589.82 3183.11,589.82 3188.1,594.81 3188.1,611.78 3184.29,615.59 3156.97,615.59 3149.65,622.91 3149.65,764.42 3129.37,784.7 U12.M18@3022.52,784.7
RMII1_TXD0: J15.13 U12.P16 | length 1328.7
  Top Layer w6.5: v1(2564.59,-125.61) J15.13@2564.59,-72.63 ; U12.P16@2959.53,721.71 v2(2975.27,737.46)
  Bottom Layer w5: v2(2975.27,737.46) 2990.77,721.96 2990.77,630.4 2993.7,627.47 3018.53,627.47 3026.99,619.02
  Bottom Layer w6.5: v1(2564.59,-125.61) 2564.59,-87.19 2835.5,183.71 2939.44,183.71 3121.79,366.06 3121.79,564.26 3075.52,610.53 3035.48,610.53 3026.99,619.02
RMII1_TXD1: J15.15 U12.P17 | length 1345.4
  Top Layer w6.5: v1(2471.62,-72.63) J15.15@2514.59,-72.63 ; U12.P17@2991.02,721.71 v2(3006.77,705.96)
  SIGNAL2 w5: 2928.28,603 2928.28,680.89 2937.36,689.97 2990.77,689.97 v2(3006.77,705.96)
  SIGNAL2 w6.5: v1(2471.62,-72.63) 2471.62,6.07 2559.73,94.18 2566.79,94.18 2589.12,71.85 2594.51,71.85 2606.51,83.85 2606.51,89.23 2584.17,111.57 2584.17,118.63 2596.92,131.37 2602.31,131.37 2622.17,111.51 2629.23,111.51 2641.23,123.51 2641.23,128.9 2621.37,148.76 2621.37,155.82 2633.37,167.82 2638.75,167.82 2658.61,147.96 2665.67,147.96 2677.67,159.96 2677.67,165.35 2657.81,185.21 2657.81,192.27 2669.81,204.27 2675.2,204.27 2691.52,187.94 2698.58,187.94 2710.58,199.94 2710.58,219.85 2810,319.26 2810,346.39 2843.43,379.81 2862.66,379.81 2891.74,408.9 2891.74,502.87 2928.28,539.41 2928.28,603
SHUNT_ENABLE: R78.1 U12.K1 | length 3091.5
  Top Layer w6.5: v1(2409.95,847.69) U12.K1@2487.08,847.69 ; R78.1@4143.03,2001.28 4143.03,1999.36 4162.99,1979.4 4162.99,1974.47 v1(4165.58,1971.88)
  SIGNAL2 w6.5: v1(2409.95,847.69) 2366.06,891.59 2366.06,1489.19 2451.17,1574.3 2663.13,1574.3 2750.57,1486.86 3265.8,1486.86 3317.35,1435.3 3583.61,1435.3 3669.36,1521.06 3669.36,1864.69 3759.8,1955.13 4148.82,1955.13 v1(4165.58,1971.88)
SOC_CLOCKOUT0: J15.12 U12.M2 U12.R17 | length 2408.6
  Top Layer w6.5: v2(2502.83,768.95) U12.M2@2518.58,784.7 ; v1(2614.59,19.47) J15.12@2614.59,72.44 ; U12.R17@2991.02,690.21 v2(3006.77,674.47)
  SIGNAL2 w5: 2959.77,603.61 2959.77,660.14 2974.1,674.47 v2(3006.77,674.47)
  SIGNAL2 w6.5: v1(2614.59,19.47) 2641.81,46.69 2654.94,46.69 2667.3,34.33 2672.68,34.33 2687.23,48.87 2687.23,54.26 2664.89,76.59 2664.89,83.65 2677.64,96.4 2683.02,96.4 2702.88,76.54 2709.94,76.54 2721.94,88.54 2721.94,93.92 2702.08,113.79 2702.08,120.84 2714.08,132.85 2719.47,132.85 2739.33,112.98 2746.39,112.98 2758.39,124.99 2758.39,130.37 2738.53,150.23 2738.53,157.29 2750.53,169.29 2755.91,169.29 2772.24,152.97 2779.3,152.97 2791.3,164.97 2791.3,184.87 2829.26,222.84 2829.26,295.87 2867.58,334.18 2867.58,345.48 2945.14,423.04 2945.14,539.4 2959.77,554.03 2959.77,603.61
  Bottom Layer w6.5: v2(2502.83,768.95) 2480.18,746.3 2480.18,683.96 2460.25,664.03 2440.47,664.03 2349.33,664.03 2319.05,633.75 2319.05,298.01 2429.72,187.34 2674,187.34 2704.37,156.97 2704.37,125.84 2686.9,108.38 2647.42,108.38 2614.59,75.54 v1(2614.59,19.47)
SOC_JTAG_TCK: J12.11 U12.B3 | length 2996.8
  Top Layer w6.5: J12.11@665.94,-101.59 v1(665.94,-20.09) ; v2(2534.33,1115.41) U12.B3@2550.08,1099.66
  SIGNAL1 w6.5: v1(665.94,-20.09) 665.94,59.42 681.41,74.89 1015.89,74.89 1185.73,-94.95 1190.43,-99.65 1639.34,-99.65 1686.43,-52.56 1686.43,-36.24 1686.43,328.73 2018.59,660.89 2018.59,859.29 2064.23,904.93 2159.89,904.93 2229.99,975.03 2330.53,975.03 2361.29,1005.79 2464.83,1005.79 2534.33,1075.29 v2(2534.33,1115.41)
SOC_JTAG_TDI: J12.3 U12.C5 | length 3021.9
  Top Layer w6.5: J12.3@465.94,-101.59 v1(465.94,-20.09) ; v2(2597.32,1083.91) U12.C5@2613.07,1068.17
  SIGNAL1 w6.5: v1(465.94,-20.09) 585.8,-139.95 1629.98,-139.95 1640.07,-139.95 1738.37,-41.65 1738.37,-31.56 1738.37,200.63 2217.87,680.13 2226.13,680.13 2267.96,721.96 2267.96,872.59 2298.36,902.98 2327.55,902.98 2393.66,969.09 2482.49,969.09 v2(2597.32,1083.91)
SOC_JTAG_TDO: J12.7 U12.C4 | length 2990.6
  Top Layer w6.5: J12.7@565.94,-101.59 v1(565.94,-20.09) ; v2(2565.82,1083.91) U12.C4@2581.57,1068.17
  SIGNAL1 w6.5: v1(565.94,-20.09) 621.52,-75.67 1093.45,-75.67 1131.8,-114.02 1634.56,-114.02 1645.67,-114.02 1716.6,-43.1 1716.6,-31.98 1716.6,303.64 1828.47,415.51 1835.53,415.51 1855.39,395.64 1860.77,395.64 1872.77,407.65 1872.77,414.7 1852.91,434.57 1852.91,439.95 1864.91,451.95 1871.97,451.95 1888.15,435.77 1899.54,435.77 1962.25,498.48 1962.25,550.35 2097.68,685.77 2097.68,697.69 2225.9,825.92 2225.9,884.76 2295.05,953.91 2348.38,953.91 2381.76,987.3 2469.21,987.3 v2(2565.82,1083.91)
SOC_JTAG_TMS: J12.1 U12.D5 | length 3118.9
  Top Layer w6.5: J12.1@415.94,-101.59 v1(415.94,-20.09) ; v2(2597.32,1052.42) U12.D5@2613.07,1036.67
  SIGNAL1 w6.5: v1(415.94,-20.09) 560.37,-164.52 1638.86,-164.52 1759.33,-44.05 1759.33,198.12 2191.38,630.17 2235.09,630.17 2287.43,682.52 2287.43,869.27 2303.15,884.98 2332.72,884.98 2398.8,951.06 2440.47,951.06 2495.96,951.06 2527.72,951.06 2597.32,1020.66 v2(2597.32,1052.42)
SOC_MDC: J15.5 U12.M17 | length 1383.1
  Top Layer w6.5: v1(2764.59,-125.61) J15.5@2764.59,-72.63 ; U12.M17@2991.02,784.7 v2(3006.77,768.95)
  Bottom Layer w6.5: v1(2764.59,-125.61) 2914.94,24.74 3079.45,24.74 3091.54,36.83 3091.54,166.07 3224.81,299.33 3224.81,612.38 3068.24,768.95 v2(3006.77,768.95)
SOC_MDIO: J15.7 U12.N16 | length 1416
  Top Layer w6.5: v1(2714.59,-125.61) J15.7@2714.59,-72.63 ; U12.N16@2959.53,753.21 v2(2975.27,768.95)
  Bottom Layer w6.5: v1(2714.59,-125.61) 2768.13,-72.06 2768.13,-16.03 2855.83,71.67 3062.84,71.67 3074.49,83.33 3074.49,181.83 3199.59,306.93 3199.59,597.76 3052.91,744.43 2999.79,744.43 v2(2975.27,768.95)
SOC_MMC0_CD: U12.A5
SOC_MMC0_CLK: R520.1 U12.B6 | length 2114.4
  Top Layer w6.5: v2(2628.82,1115.41) U12.B6@2644.56,1099.66
  SIGNAL1 w6.5: v1(1444.15,434.77) 1374.12,434.77 1298.43,510.46 1298.43,763.01 1337.53,802.11 1721.59,802.11 2095.86,1176.39 2227.07,1176.39 2310.9,1260.22 2509.47,1260.22 2558.83,1210.87 2577.84,1210.87 2594.42,1194.29 2594.42,1149.81 v2(2628.82,1115.41)
  Bottom Layer w6.5: v1(1444.15,434.77) R520.1@1484.27,434.77
SOC_MMC0_CMD: U12.A4 U15.P5 | length 1986.7
  Top Layer w6.5: v1(1492.14,469.61) U15.P5@1492.14,497.45 ; v1(2571.82,1186.35) 2571.82,1165.75 2581.57,1156 U12.A4@2581.57,1131.16
  SIGNAL1 w6.5: v1(1492.14,469.61) 1463.89,497.86 1404.32,497.86 1402.47,496.01 1347.28,496.01 1326.22,517.07 1326.22,762.69 1343.63,780.1 1730.68,780.1 2112.33,1161.75 2241.9,1161.75 2321.79,1241.64 2502.2,1241.64 2557.1,1186.74 2571.43,1186.74 v1(2571.82,1186.35)
SOC_MMC0_D0: U12.B5 U15.K2 | length 1804.1
  Top Layer w6.5: U15.K2@1374.03,654.93 v1(1393.72,635.25) ; v2(2597.32,1115.41) U12.B5@2613.07,1099.66
  SIGNAL1 w6.5: v1(1393.72,635.25) 1786.99,635.25 1803.05,651.31 1810.1,651.31 1829.97,631.44 1835.35,631.44 1847.35,643.45 1847.35,650.5 1827.49,670.37 1827.49,675.75 1839.49,687.75 1846.55,687.75 1866.41,667.89 1871.8,667.89 1883.8,679.89 1883.8,686.95 1863.94,706.81 1863.94,712.2 1875.94,724.2 1883,724.2 1902.86,704.34 1908.24,704.34 1920.24,716.34 1920.24,723.4 1900.38,743.26 1900.38,748.64 1912.39,760.65 1919.44,760.65 1939.3,740.78 1944.69,740.78 1956.69,752.79 1956.69,759.84 1936.83,779.71 1936.83,787.39 1956.09,806.66 1956.09,909.86 2020.86,974.63 2154.32,974.63 2274.99,1095.3 2368.2,1095.3 2431.52,1158.62 2554.11,1158.62 v2(2597.32,1115.41)
SOC_MMC0_D1: U12.B4 U15.N2 | length 1898.5
  Top Layer w6.5: U15.N2@1374.03,536.82 v1(1393.72,556.51) ; v2(2565.82,1115.41) U12.B4@2581.57,1099.66
  SIGNAL1 w6.5: v1(1393.72,556.51) 1422.28,527.94 1800.61,527.94 1807.22,534.55 1807.22,546.48 1800.77,552.93 1800.77,558.32 1812.77,570.32 1819.83,570.32 1839.69,550.46 1845.08,550.46 1857.08,562.46 1857.08,569.52 1837.22,589.38 1837.22,594.76 1849.22,606.77 1856.28,606.77 1876.14,586.9 1881.52,586.9 1893.53,598.91 1893.53,605.96 1873.66,625.83 1873.66,631.21 1885.67,643.21 1892.72,643.21 1912.59,623.35 1917.97,623.35 1929.97,635.35 1929.97,642.41 1910.11,662.27 1910.11,667.66 1922.11,679.66 1929.17,679.66 1949.03,659.8 1954.42,659.8 1966.42,671.8 1966.42,678.86 1946.56,698.72 1946.56,704.1 1958.56,716.1 1965.62,716.1 1985.48,696.24 1990.86,696.24 2002.87,708.25 2002.87,715.3 1983,735.16 1983,847.09 2090.03,954.12 2175.86,954.12 2247.73,1025.98 2380.63,1025.98 2492.21,1137.56 2543.67,1137.56 v2(2565.82,1115.41)
SOC_MMC0_D2: U12.A3 U15.K3 | length 1762
  Top Layer w6.5: U15.K3@1413.4,654.93 v1(1433.09,674.62) ; v1(2521.82,1186.35) 2550.08,1158.1 U12.A3@2550.08,1131.16
  SIGNAL1 w6.5: v1(1433.09,674.62) 1444.21,685.74 1695.38,685.74 1701.99,692.34 1701.99,704.28 1695.54,710.73 1695.54,716.11 1707.54,728.11 1714.6,728.11 1734.46,708.25 1739.85,708.25 1751.85,720.25 1751.85,727.31 1731.99,747.17 1731.99,752.56 1743.99,764.56 1751.05,764.56 1770.91,744.7 1776.29,744.7 1788.3,756.7 1788.3,763.76 1768.43,783.62 1768.43,789 1780.44,801.01 1787.49,801.01 1807.36,781.14 1812.74,781.14 1824.74,793.15 1824.74,800.2 1804.88,820.07 1804.88,825.45 1816.88,837.45 1823.94,837.45 1843.8,817.59 1849.19,817.59 1861.19,829.59 1861.19,836.65 1841.33,856.51 1841.33,861.9 1853.33,873.9 1860.39,873.9 1880.25,854.04 1885.63,854.04 1897.64,866.04 1897.64,873.1 1877.77,892.96 1877.77,902.26 2084.34,1108.82 2217.45,1108.82 2323.88,1215.25 2492.92,1215.25 v1(2521.82,1186.35)
SOC_MMC0_D3: U12.A2 U15.N3 | length 1898.9
  Top Layer w6.5: v1(1393.72,517.14) U15.N3@1413.4,536.82 ; v1@2471.96,1186.21 2487.03,1186.21 2518.58,1154.66 U12.A2@2518.58,1131.16
  SIGNAL1 w6.5: v1(1393.72,517.14) 1364.99,545.87 1364.99,646.16 1378.56,659.74 1407.84,659.74 1415.42,652.16 1755.6,652.16 1762.21,658.77 1762.21,670.7 1755.76,677.15 1755.76,682.53 1767.76,694.53 1774.82,694.53 1794.68,674.67 1800.07,674.67 1812.07,686.67 1812.07,693.73 1792.21,713.59 1792.21,718.98 1804.21,730.98 1811.27,730.98 1831.13,711.12 1836.51,711.12 1848.52,723.12 1848.52,730.18 1828.66,750.04 1828.66,755.43 1840.66,767.43 1847.72,767.43 1867.58,747.57 1872.96,747.57 1884.96,759.57 1884.96,766.63 1865.1,786.49 1865.1,791.87 1877.1,803.87 1884.16,803.87 1904.02,784.01 1909.41,784.01 1921.41,796.01 1921.41,803.07 1901.55,822.93 1901.55,828.32 1934.17,860.95 1934.17,917.5 2044.58,1027.91 2161.98,1027.91 2320.42,1186.35 v1(2471.82,1186.35)
SOC_MMC0_WP: R29.1 U12.C6 | length 204.1
  Top Layer w6.5: R29.1@2631.07,1235.38 v1(2661.1,1235.38) ; U12.C6@2644.56,1068.17 v2(2660.31,1083.91)
  SIGNAL1 w6.5: v2(2660.31,1083.91) 2660.31,1234.59 v1(2661.1,1235.38)
Soc_PORz: R46.2 R73.1 U6.7 U12.R2 | length 3498
  Top Layer w6.5: R73.1@751.86,575.8 747.84,579.82 R46.2@747.84,638.09 1160.36,1050.6 1853.77,1050.6 1958.85,1155.68 1958.85,1566.64 v1(1922.94,1602.55) 1909.87,1615.62 U6.7@1870.52,1615.62 ; v2(2502.83,674.47) U12.R2@2518.58,690.21
  SIGNAL2 w6.5: v1(1922.94,1602.55) 1960.24,1565.25 1960.24,768.61 2097.64,631.21 2279.35,631.21 2309.32,661.17 2489.54,661.17 v2(2502.83,674.47)
SOC_QSPI0_CLK: R16.1 U12.N2 | length 1360.3
  Top Layer w6.5: R16.1@2030.72,1540.94 v1(2030.72,1576.69) ; v2(2502.83,737.46) U12.N2@2518.58,753.21
  SIGNAL2 w6.5: v1(2030.72,1576.69) 1998.82,1544.79 1998.82,896.27 2114.68,780.41 2203.37,780.41 2293.2,690.59 2361.29,690.59 2385.44,714.74 2480.11,714.74 v2(2502.83,737.46)
SOC_QSPI0_CS0: R26.1 U7.1 U12.P1 | length 890
  Top Layer w6.5: U12.P1@2487.08,721.71 2466.43,721.71 2434.95,690.23 2409.95,690.23 2384.53,715.65 2384.53,1241.91 2446,1303.38 U7.1@2446,1393.98 2481.03,1393.98 R26.1@2506.06,1393.98
SOC_QSPI0_D0: U7.5 U12.N1 U18.13 | length 3589.5
  Top Layer w6.5: v1(512.86,300.6) 524.3,312.04 U18.13@542.31,312.04 ; U7.5@2138.92,1543.98 v1(2138.92,1570.11) ; v1(2409.95,739.89) 2452.04,739.89 2465.35,753.21 U12.N1@2487.08,753.21
  SIGNAL1 w6.5: v1(512.86,300.6) 478.53,300.6 458.36,320.77 458.36,436.67 1266.56,1244.87 1724.98,1244.87 1997.3,1517.2 2104.47,1517.2 2138.92,1551.64 v1(2138.92,1570.11)
  SIGNAL2 w6.5: v1(2138.92,1570.11) 2138.92,1541.38 2039.89,1442.35 2039.89,969.36 2116.41,892.85 2171.77,892.85 2298.79,765.83 2349.79,765.83 2375.73,739.89 v1(2409.95,739.89)
SOC_QSPI0_D1: U7.2 U12.N4 U18.12 | length 3497.3
  Top Layer w6.5: v1(486.05,331.74) U18.12@542.31,331.72 ; U7.2@2446,1443.98 v1(2481.03,1443.98) ; v2(2565.82,737.46) U12.N4@2581.57,753.21
  SIGNAL1 w6.5: v1(486.05,331.74) 505.62,331.74 542.28,368.4 542.28,467.96 1287.41,1213.09 1727.44,1213.09 2005.97,1491.62 2433.39,1491.62 v1(2481.03,1443.98)
  SIGNAL2 w5: 2550.32,811.93 2550.32,752.96 v2(2565.82,737.46)
  SIGNAL2 w6.5: v1(2481.03,1443.98) 2396.49,1359.43 2396.49,967.31 2459.64,904.16 2513.28,850.52 2538.74,850.52 2554.69,834.57 2554.69,828.82 2550.32,824.46 2550.32,811.93
SOC_QSPI0_D2: R23.1 U7.3 U12.M4 | length 938.2
  Top Layer w6.5: U7.3@2446,1493.98 v1(2481.03,1493.98) R23.1@2506.06,1493.98 ; v2(2565.82,768.95) U12.M4@2581.57,784.7
  SIGNAL2 w5: v2(2565.82,768.95) 2581.52,784.65 2581.52,816.63
  SIGNAL2 w6.5: v1(2481.03,1493.98) 2511.35,1463.65 2511.35,1363.47 2411.46,1263.58 2411.46,1018.14 2459.64,969.96 2528.49,901.11 2528.49,877.46 2581.52,824.43 2581.52,816.63
SOC_QSPI0_D3: R25.1 U7.7 U12.P3 | length 1049.1
  Top Layer w6.5: R25.1@2078.92,1431.97 2090.92,1443.98 v1(2104.09,1443.98) U7.7@2138.92,1443.98 ; v2(2534.33,737.46) U12.P3@2550.08,721.71
  SIGNAL2 w5: 2495.86,752.96 2509.25,752.96 2517.09,745.12 2526.67,745.12 v2(2534.33,737.46)
  SIGNAL2 w6.5: v1(2104.09,1443.98) 2150.06,1398.01 2150.06,1211.95 2250.72,1111.29 2250.72,889.43 2311.14,829.02 2333.08,829.02 2401.08,761.02 2463.51,761.02 2471.57,752.96 2495.86,752.96
SOP0: J10.1 R70.1 U18.2 | length 512.5
  Top Layer w6.5: J10.1@240.71,260.2 R70.1@352.13,260.2 v1(352.13,231.93) ; U18.2@632.86,312.04 650.87,312 v1(662.3,300.56)
  SIGNAL1 w6.5: v1(352.13,231.93) 449.75,231.93 487.97,270.15 546.67,270.15 577.08,300.56 v1(662.3,300.56)
SOP1: J10.3 R67.1 U18.3 | length 650
  Top Layer w6.5: J10.3@240.71,360.2 R67.1@352.13,360.2 v1(352.13,331.93) ; 665.81,331.72 U18.3@632.86,331.72 v1(689.12,331.7)
  SIGNAL2 w6.5: v1(352.13,331.93) 352.13,362.95 400.59,411.41 587.86,411.41 667.57,331.7 v1(689.12,331.7)
SOP2: J10.5 R63.1 U18.4 | length 583.3
  Top Layer w6.5: J10.5@240.71,460.2 R63.1@352.13,460.2 v1(352.13,431.93) ; U18.4@632.84,351.39 673.59,351.39 v1(692.66,370.45)
  Bottom Layer w6.5: v1(352.13,431.93) 563.37,431.93 636.75,358.55 680.75,358.55 v1(692.66,370.45)
SOP3: J10.7 R47.1 U18.5 | length 545.9
  Top Layer w6.5: J10.7@240.71,560.2 R47.1@352.13,560.2 v1(352.13,531.93) ; U18.5@632.86,371.09 650.87,371.09 v1(662.3,382.53)
  Bottom Layer w6.5: v1(352.13,531.93) 386.46,531.93 429.95,488.45 537.46,488.45 643.36,382.55 v1(662.3,382.53)
SPI0_CLK: J11.7 U12.A11 U18.11 | length 3903.2
  Top Layer w6.5: v1(482.51,370.49) 501.57,351.43 U18.11@542.31,351.41 ; v1(2786.82,1186.35) 2802.05,1171.13 U12.A11@2802.05,1131.16
  SIGNAL1 w6.5: J11.7@1309.08,52.39 1309.08,302.26 1235.57,375.77 1235.57,821.74 1383.16,969.33 1715.71,969.33 2074.48,1328.1 2175.99,1328.1 2186.83,1338.95 2272.19,1338.95 2297.96,1313.17 2753.66,1313.17 2786.82,1280.01 v1(2786.82,1186.35)
  Bottom Layer w6.5: v1(482.51,370.49) 458.2,346.18 458.2,211.4 531.16,138.44 1226.4,138.44 J11.7@1313.4,51.43
SPI0_CS0: J11.9 U12.C11 | length 2887.2
  Top Layer w6.5: U12.C11@2802.05,1068.17 v2(2817.79,1083.91)
  SIGNAL1 w6.5: J11.9@1209.08,52.39 1212.67,55.98 1212.67,847.69 1385.29,1020.3 1718.06,1020.3 2043.26,1345.5 2109.61,1345.5 2139.2,1375.09 2276.72,1375.09 2321.1,1330.72 2764.98,1330.72 2813.93,1281.77 2813.93,1153.93 2801.54,1141.55 2801.54,1100.16 v2(2817.79,1083.91)
SPI0_D0: J11.5 U12.C10 U18.10 | length 4120.6
  Top Layer w6.5: v1(512.86,382.57) 524.3,371.14 U18.10@542.31,371.09 ; U12.C10@2770.55,1068.17 v2(2786.3,1083.91)
  SIGNAL1 w6.5: J11.5@1409.08,52.39 1409.08,288.53 1260.19,437.42 1260.19,796.92 1371.68,908.41 1797.22,908.41 2081.99,1193.18 2210.39,1193.18 2314.21,1297 2695.79,1297 2713.09,1279.71 2713.09,1157.13 v2(2786.3,1083.91)
  Bottom Layer w6.5: v1(512.86,382.57) 496,399.43 465.89,399.43 436.86,370.4 436.86,202.01 526.73,112.14 1216.73,112.14 1232.05,96.81 1232.2,96.81 1263.35,65.66 1263.35,31.52 1294.49,0.37 1362.34,0.37 J11.5@1413.4,51.43
SPI0_D1: J11.8 U12.B11 | length 3216.7
  Top Layer w6.5: U12.B11@2802.05,1099.66 v2(2817.79,1115.41)
  SIGNAL1 w6.5: J11.8@1309.08,-47.61 1259.22,2.25 1180.71,2.25 1147.99,34.96 1147.99,894.98 1300.49,1047.48 1693.98,1047.48 2066.89,1420.39 2489.92,1420.39 2501.9,1408.41 2716.07,1408.41 2833.82,1290.66 2833.82,1131.44 v2(2817.79,1115.41)
STAT0_LED: R32.2 U12.B14 | length 126.5
  Top Layer w6.5: U12.B14@2897.5,1099.66 v2@2912.65,1114.82
  Top Layer w10: U12.B14@2896.53,1099.66 U12.B14@2897.5,1099.66 ; R32.2@2911.38,1217.05 2912.47,1215.96 2912.47,1190.82 v2(2913.56,1189.73) ; v2@2912.65,1114.82 v2(2913.61,1114.82)
  SIGNAL1 w6.5: v2(2913.61,1114.82) v2(2913.56,1189.73)
STAT1_LED: R31.2 U12.A14 | length 111.9
  Top Layer w6.5: R31.2@2833.82,1217.05 2833.82,1215.09 2896.53,1152.37 U12.A14@2896.53,1131.16
UART0_RXD: J14.14 U12.A7 | length 2093.4
  Top Layer w6.5: J14.14@1981.28,72.44 v1(1981.28,125.42) ; U12.A7@2676.06,1131.16 2676.06,1175.49 2686.82,1186.25 v1(2686.82,1186.35)
  Bottom Layer w6.5: v1(1981.28,125.42) 1913.04,193.66 1913.04,1174.57 2075.29,1336.83 2162.99,1336.83 2217.04,1282.78 2384.89,1282.78 2432.34,1235.34 2623.49,1235.34 2670.56,1188.26 2684.91,1188.26 v1(2686.82,1186.35)
UART0_TXD: J14.12 U12.A6 | length 1831.9
  Top Layer w6.5: J14.12@2031.28,72.44 v1(2031.28,125.42) ; v1(2636.82,1186.35) 2636.82,1169.04 2644.56,1161.3 U12.A6@2644.56,1131.16
  Bottom Layer w6.5: v1(2031.28,125.42) 1948.36,208.34 1948.36,1033 2102.5,1187.14 2413.88,1187.14 2442,1215.25 2609.28,1215.25 2638.18,1186.35 v1(2636.82,1186.35)
VBIAS: C25.2 C64.1 J9.D15 R19.2 R42.2 TP8.1 U9.13 | length 275.3
  Top Layer w15: C64.1@3762.04,-1.74 v1(3797.78,-1.74) ; 4072.18,1452.7 4090.85,1434.04 U9.13@4115.92,1434.04 C25.2@4115.92,1489.65 ; v1(4078.14,1489.65) C25.2@4115.92,1489.65 ; v1(4153.71,1489.65) C25.2@4115.92,1489.65 ; v1(4218.45,1500.46) R19.2@4247.46,1500.46 ; v1(4348.41,832.48) R42.2@4348.41,860.32
  other v5: 3988.89,44.37
VDDA1V8_OSC_PLL_F: C553.1 FB2.2 U12.R4 | length 423.7
  Top Layer w6.5: v3(2565.82,674.47) U12.R4@2581.57,690.21
  Top Layer w20: FB2.2@2251.51,513.33 v1(2251.51,548.07)
  SIGNAL2 w5: 2525.52,658.67 2550.03,658.67 v3(2565.82,674.47)
  SIGNAL2 w10: v1(2251.51,548.07) 2333.18,629.75 2485.88,629.75 2514.8,658.67 2525.52,658.67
